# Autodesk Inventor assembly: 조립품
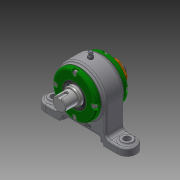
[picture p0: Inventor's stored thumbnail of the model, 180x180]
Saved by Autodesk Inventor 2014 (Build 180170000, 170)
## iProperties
Created: 2019-05
Part Number: 조립품
Document SubType Name: Assembly
Designer: kh
Author: kh
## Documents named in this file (13)
- C:\Users\kh\Desktop\490504V1018\조립품.iam
- C:\Users\kh\Desktop\490504V1018\본체.ipt
- C:\Users\kh\Desktop\490504V1018\개스킷.ipt
- C:\Users\kh\Desktop\490504V1018\그리스니플 M6.ipt
- 그리스니플  M6.ipt
- C:\Users\kh\Desktop\490504V1018\그리스니플개스킷.ipt
- C:\Users\kh\Desktop\490504V1018\베어링너트.ipt
- C:\Users\kh\Desktop\490504V1018\볼트 M4.ipt
- C:\Users\kh\Desktop\490504V1018\앵귤러 볼 베어링 7205.ipt
- C:\Users\kh\Desktop\490504V1018\오일 실 28 40 5 B.ipt
- C:\Users\kh\Desktop\490504V1018\축.ipt
- C:\Users\kh\Desktop\490504V1018\칼라.ipt
- C:\Users\kh\Desktop\490504V1018\커버.ipt
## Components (4 placed, 3 different names)
1. 개스킷:1 — Insert:1, Mate:1, Insert:3
2. 그리스니플  M6:1 — Insert:13, Angle:3
3. 그리스니플개스킷:1 — Insert:12, Insert:13
4. 개스킷:2 — Insert:2, Mate:2, Insert:4
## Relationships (9: Insert 6, Mate 2, Angle 1)
- Insert:1: 개스킷:1
- Insert:2: 개스킷:2
- Mate:1: 개스킷:1
- Mate:2: 개스킷:2
- Insert:3: 개스킷:1
- Insert:4: 개스킷:2
- Insert:12: 그리스니플개스킷:1
- Insert:13: 그리스니플  M6:1 ↔ 그리스니플개스킷:1
- Angle:3: 그리스니플  M6:1
